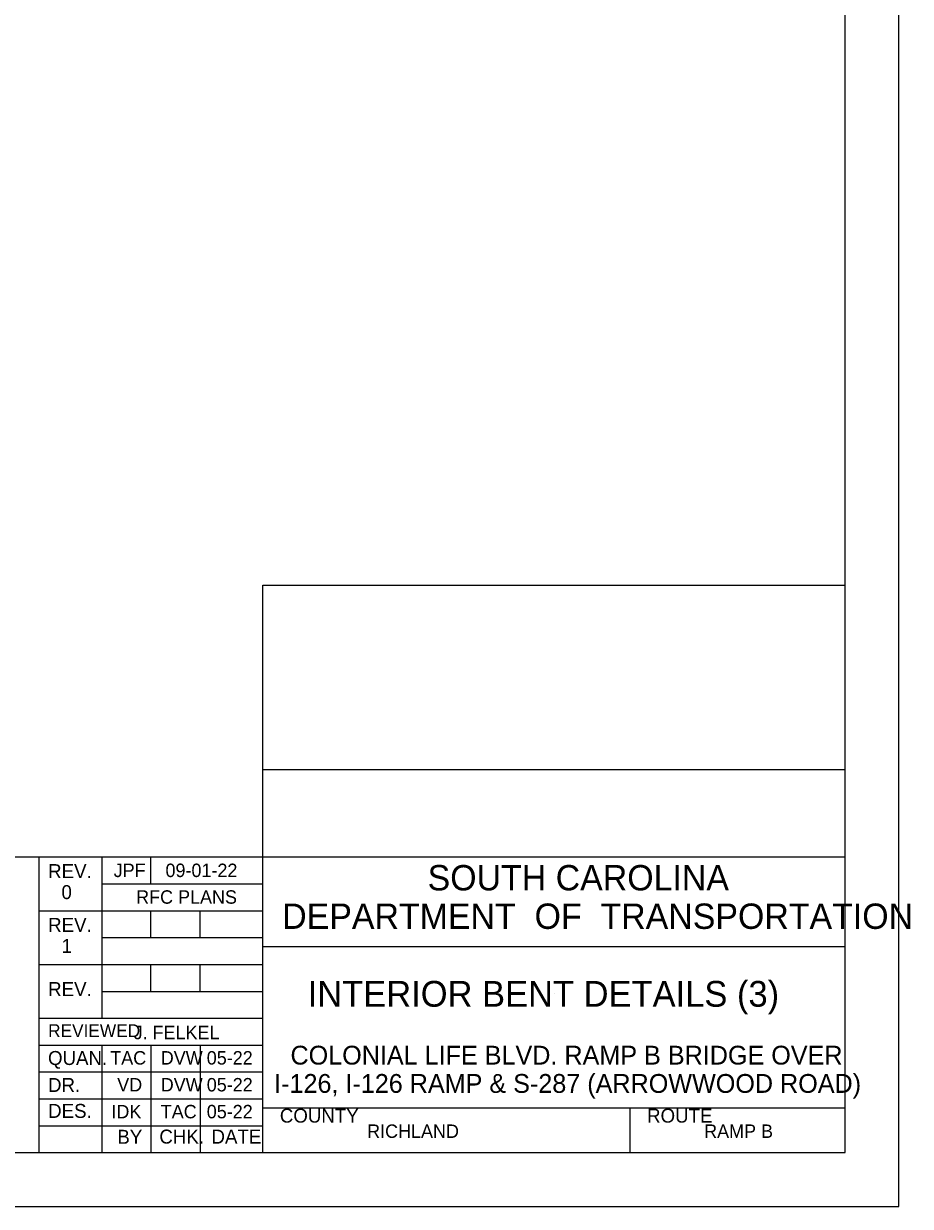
# Model space of a CAD drawing. Extents: x 1970675.2 to 1970711.3, y 796145.2 to 796167.2.
# Drawn here: x 1970703.09 to 1970711.34, y 796145.25 to 796156.25 of the extents above; entities that cross this region are included whole.
import ezdxf

# ---------------------------------------------------------------- set-up
doc = ezdxf.new("R2010")
doc.units = 0
for name, color, linetype in [('BR_BORDER LINES', 7, 'Continuous'), ('BR_TEXT', 7, 'Continuous'), ('Level 31', 7, 'Continuous')]:
    doc.layers.add(name, color=color, linetype=linetype)

msp = doc.modelspace()

# ---------------------------------------------------------------- linework, layer by layer
at = {"layer": 'BR_BORDER LINES'}
for p, q in [((1970710.736, 796145.746), (1970710.736, 796166.746)), ((1970705.319, 796145.746), (1970705.319, 796151.023)), ((1970705.319, 796151.023), (1970710.736, 796151.023)), ((1970705.319, 796149.308), (1970710.736, 796149.308)), ((1970697.87, 796148.496), (1970703.236, 796148.496)), ((1970703.236, 796145.746), (1970703.236, 796148.496)), ((1970703.236, 796148.496), (1970710.736, 796148.496)), ((1970703.819, 796148.496), (1970703.819, 796146.996)), ((1970704.277, 796148.246), (1970704.277, 796148.496)), ((1970703.819, 796148.246), (1970705.319, 796148.246)), ((1970703.236, 796147.996), (1970705.319, 796147.996)), ((1970704.277, 796147.746), (1970704.277, 796147.996)), ((1970704.736, 796147.746), (1970704.736, 796147.996)), ((1970703.819, 796147.746), (1970705.319, 796147.746)), ((1970705.319, 796147.663), (1970705.319, 796147.663)), ((1970705.319, 796147.663), (1970710.736, 796147.663)), ((1970703.236, 796147.496), (1970705.319, 796147.496)), ((1970704.277, 796147.246), (1970704.277, 796147.496)), ((1970704.736, 796147.246), (1970704.736, 796147.496)), ((1970703.819, 796147.246), (1970705.319, 796147.246)), ((1970703.236, 796146.996), (1970705.319, 796146.996)), ((1970703.236, 796146.746), (1970705.319, 796146.746)), ((1970703.819, 796146.746), (1970703.819, 796145.746)), ((1970704.277, 796146.746), (1970704.277, 796145.746)), ((1970704.736, 796146.746), (1970704.736, 796145.746)), ((1970703.236, 796146.496), (1970705.319, 796146.496)), ((1970703.236, 796146.246), (1970705.319, 796146.246)), ((1970705.319, 796146.163), (1970710.736, 796146.163)), ((1970705.417, 796146.163), (1970710.736, 796146.163)), ((1970708.736, 796145.746), (1970708.736, 796146.163)), ((1970703.236, 796145.996), (1970705.319, 796145.996)), ((1970677.07, 796145.746), (1970710.736, 796145.746))]:
    msp.add_line(p, q, dxfattribs=at)
at = {"layer": 'Level 31'}
msp.add_line((1970708.028, 796147.223), (1970708.028, 796147.223), dxfattribs=at)
msp.add_lwpolyline([(1970675.236, 796145.246), (1970711.236, 796145.246), (1970711.236, 796167.246), (1970675.236, 796167.246)], close=True, dxfattribs=at)

# ---------------------------------------------------------------- texts
at = {"layer": 'BR_TEXT'}
for s, height, p in [('REV.', 0.13, (1970703.32, 796148.299)), ('JPF', 0.125, (1970703.93, 796148.309)), ('09-01-22', 0.125, (1970704.412, 796148.309)), ('SOUTH CAROLINA', 0.23587, (1970706.851, 796148.185)), ('0', 0.13, (1970703.444, 796148.104)), ('RFC PLANS', 0.125, (1970704.139, 796148.061)), ('DEPARTMENT  OF  TRANSPORTATION', 0.23587, (1970705.498, 796147.827)), ('REV.', 0.13, (1970703.32, 796147.799)), ('1', 0.13, (1970703.446, 796147.604)), ('INTERIOR BENT DETAILS (3)', 0.24, (1970705.735, 796147.103)), ('REV.', 0.13, (1970703.32, 796147.202)), ('REVIEWED', 0.12, (1970703.32, 796146.82)), ('J. FELKEL', 0.125, (1970704.115, 796146.801)), ('QUAN.', 0.13, (1970703.319, 796146.561)), ('TAC', 0.125, (1970703.898, 796146.565)), ('DVW', 0.125, (1970704.368, 796146.565)), ('05-22', 0.125, (1970704.796, 796146.565)), ('COLONIAL LIFE BLVD. RAMP B BRIDGE OVER', 0.175, (1970705.575, 796146.565)), ('I-126, I-126 RAMP & S-287 (ARROWWOOD ROAD) ', 0.175, (1970705.423, 796146.302)), ('DR.', 0.13, (1970703.319, 796146.31)), ('VD', 0.125, (1970703.963, 796146.315)), ('DVW', 0.125, (1970704.368, 796146.315)), ('05-22', 0.125, (1970704.796, 796146.315)), ('DES.', 0.13, (1970703.32, 796146.069)), ('IDK', 0.125, (1970703.909, 796146.065)), ('TAC', 0.125, (1970704.368, 796146.065)), ('05-22', 0.125, (1970704.796, 796146.065)), ('COUNTY', 0.13, (1970705.476, 796146.025)), ('ROUTE', 0.13, (1970708.893, 796146.025)), ('BY', 0.13, (1970703.964, 796145.828)), ('CHK.', 0.13, (1970704.355, 796145.83)), ('DATE', 0.13, (1970704.84, 796145.83)), ('RICHLAND', 0.125, (1970706.288, 796145.883)), ('RAMP B', 0.125, (1970709.424, 796145.883))]:
    msp.add_text(s, height=height, dxfattribs=at).set_placement(p)

doc.saveas('drawing.dxf')
